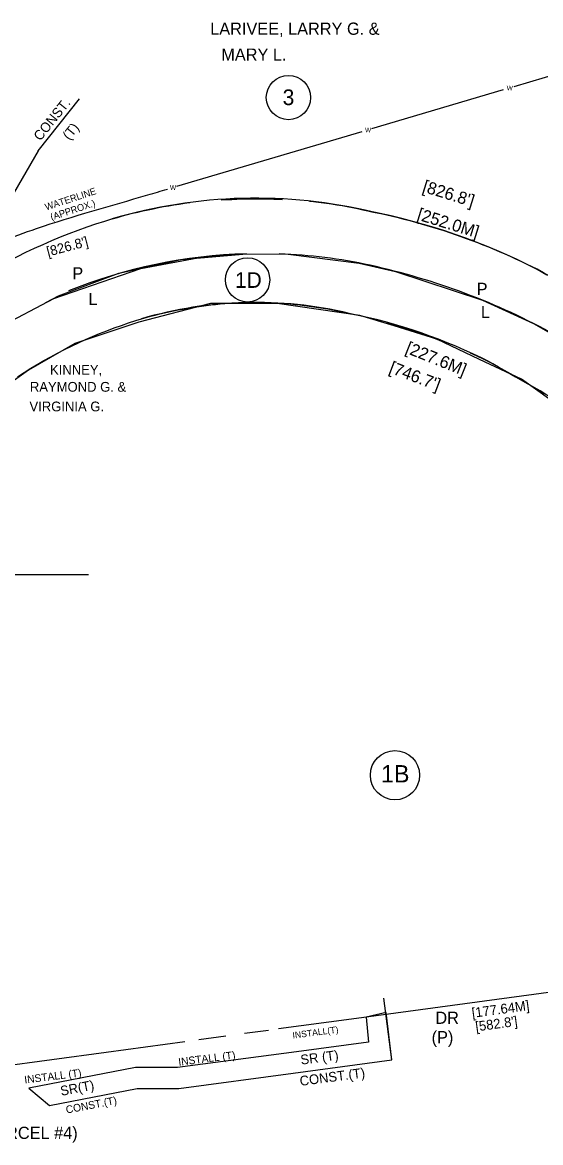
# Model space of a CAD drawing. Extents: x 624 to 1448, y 1599 to 1865.
# Drawn here: x 1071.5 to 1147.3, y 1694.1 to 1857.9 of the extents above; entities that cross this region are included whole.
import ezdxf

# ---------------------------------------------------------------- set-up
doc = ezdxf.new("R2010")
doc.units = 0
for name, color, linetype in [('C_I', 7, 'Continuous'), ('C_TIC', 7, 'Continuous'), ('L_A', 7, 'Continuous'), ('L_C', 7, 'Continuous'), ('L_I', 7, 'Continuous'), ('Level 20', 7, 'Continuous'), ('ODIML_P', 7, 'Continuous')]:
    doc.layers.add(name, color=color, linetype=linetype)

msp = doc.modelspace()

# ---------------------------------------------------------------- linework, layer by layer
at = {"layer": 'C_I'}
for p, q in [((1143.46, 1848.56), (1150.35, 1850.6)), ((1122.63, 1842.39), (1141.9, 1848.1)), ((1073.8, 1839.17), (1079.89, 1846.77)), ((1094.12, 1833.96), (1121.21, 1841.98)), ((1073.8, 1839.17), (1063.81, 1821.9))]:
    msp.add_line(p, q, dxfattribs=at)
for points in [[(1111.14, 1704.26), (1125.57, 1706.19), (1124.39, 1715.24)], [(1090.58, 1702.03), (1094.42, 1702.03), (1111.14, 1704.26)], [(1075.49, 1699.53), (1088.31, 1702.03), (1090.58, 1702.03)]]:
    msp.add_lwpolyline(points, dxfattribs=at)
msp.add_spline([(1063.22, 1823.93), (1073.58, 1827.78), (1089.86, 1832.7), (1092.73, 1833.55)], degree=3, dxfattribs=at)
at = {"layer": 'C_TIC'}
for p, q in [((1119.66, 1712.21), (1156.34, 1717.18)), ((1108.99, 1710.77), (1119.66, 1712.21)), ((1103.99, 1710.09), (1107.51, 1710.56)), ((1083.77, 1707.35), (1095.29, 1708.91)), ((1097.31, 1709.18), (1101.26, 1709.72)), ((1047.93, 1702.5), (1083.77, 1707.35))]:
    msp.add_line(p, q, dxfattribs=at)
at = {"layer": 'L_A'}
for points in [[(1068.14, 1813.35), (1076.1, 1817.56), (1088.82, 1821.95), (1097.94, 1823.65), (1104.33, 1824.09), (1110.38, 1824.03), (1120.8, 1822.73), (1126.12, 1821.52), (1138.82, 1817.31), (1146.28, 1813.9), (1154.59, 1809.17)], [(1150.85, 1801.23), (1144.54, 1805.75), (1138.38, 1808.63), (1132.15, 1811.59), (1125.92, 1813.54), (1120.89, 1815.06), (1108.79, 1816.82), (1099.05, 1816.82), (1088.53, 1814.09), (1079.19, 1810.97), (1072.4, 1807.06), (1066.34, 1802.78)]]:
    msp.add_lwpolyline(points, dxfattribs=at)
at = {"layer": 'L_C'}
msp.add_line((1050.04, 1777.2), (1081.2, 1777.2), dxfattribs=at)
for centre, radius in [((1110.44, 1846.94), 3.24), ((1104.46, 1820.28), 3.24), ((1126.02, 1747.83), 3.6)]:
    msp.add_circle(centre, radius, dxfattribs=at)
at = {"layer": 'L_I'}
msp.add_lwpolyline([(1074.94, 1816.96), (1076.79, 1817.92), (1085.63, 1821.24), (1094.76, 1823.26), (1104.33, 1824.09)], dxfattribs=at)
for centre, radius, start, end in [((1106.39, 1749.13), 75, 91.631, 112.0208), ((1106.39, 1749.13), 75, 77.7037, 87.9317), ((1101.07, 1724.7), 100, 61.0375, 77.7037)]:
    msp.add_arc(centre, radius, start, end, dxfattribs=at)
at = {"layer": 'Level 20'}
msp.add_lwpolyline([(1072.47, 1702.05), (1075.49, 1699.53), (1088.31, 1702.03), (1094.42, 1702.03), (1111.14, 1704.26), (1125.57, 1706.19), (1124.75, 1713.13), (1121.79, 1712.47), (1122.16, 1708.81), (1111.62, 1707.4), (1094.21, 1705.07), (1088.08, 1705.09)], close=True, dxfattribs=at)
at = {"layer": 'ODIML_P'}
for points in [[(1070.8, 1823.7), (1072.04, 1824.31), (1073.29, 1824.9), (1074.55, 1825.47), (1075.81, 1826.02), (1077.09, 1826.55), (1078.38, 1827.06), (1079.67, 1827.55), (1080.97, 1828.01), (1082.28, 1828.46), (1083.6, 1828.88), (1084.6, 1829.18), (1084.66, 1829.2), (1085.41, 1829.42), (1086.15, 1829.62), (1086.9, 1829.82), (1087.64, 1830.01), (1088.39, 1830.19), (1089.15, 1830.37), (1089.9, 1830.53), (1090.66, 1830.69), (1091.41, 1830.84), (1092.17, 1830.99), (1092.93, 1831.12), (1093.69, 1831.25), (1094.45, 1831.37), (1095.22, 1831.48), (1095.98, 1831.59), (1096.01, 1831.59)], [(1100.61, 1831.97), (1101.37, 1832.01), (1102.14, 1832.05), (1102.91, 1832.09), (1103.68, 1832.11), (1104.45, 1832.13), (1105.22, 1832.13), (1105.99, 1832.13), (1106.76, 1832.13), (1107.53, 1832.11), (1108.3, 1832.09), (1109.07, 1832.06), (1109.59, 1832.03)], [(1113.54, 1831.79), (1113.69, 1831.77), (1114.46, 1831.69), (1115.23, 1831.59), (1115.99, 1831.49), (1116.75, 1831.38), (1117.52, 1831.26), (1118.28, 1831.13), (1119.04, 1830.99), (1119.8, 1830.85), (1120.55, 1830.7), (1121.31, 1830.54), (1122.06, 1830.37), (1122.81, 1830.2), (1122.85, 1830.19), (1122.27, 1830.32), (1123.12, 1830.15), (1123.96, 1829.97), (1124.81, 1829.78), (1125.66, 1829.59), (1126.5, 1829.38), (1127.34, 1829.17), (1128.18, 1828.95), (1129.02, 1828.73), (1129.85, 1828.49), (1130.68, 1828.25), (1131.51, 1828), (1132.34, 1827.75), (1133.17, 1827.48), (1133.99, 1827.21), (1134.81, 1826.93), (1135.63, 1826.64), (1136.44, 1826.35), (1137.26, 1826.05), (1138.07, 1825.74), (1138.87, 1825.42), (1139.68, 1825.1), (1140.48, 1824.76), (1141.28, 1824.42), (1142.07, 1824.08), (1142.86, 1823.72), (1143.65, 1823.36), (1144.43, 1822.99), (1145.22, 1822.62), (1145.99, 1822.23), (1146.77, 1821.84), (1146.82, 1821.82), (1148.25, 1821.02)], [(1058.72, 1816.36), (1062.43, 1818.85), (1063.59, 1819.6), (1064.77, 1820.33), (1065.95, 1821.05), (1067.14, 1821.74), (1068.35, 1822.41), (1069.57, 1823.06), (1070.8, 1823.7), (1072.04, 1824.31), (1073.29, 1824.9), (1074.55, 1825.47), (1075.81, 1826.02), (1077.09, 1826.55), (1078.38, 1827.06), (1079.67, 1827.55), (1080.97, 1828.01), (1082.28, 1828.46), (1083.6, 1828.88), (1084.6, 1829.18)], [(1073.24, 1807.65), (1073.7, 1807.92), (1074.67, 1808.49), (1075.66, 1809.04), (1076.66, 1809.57), (1077.66, 1810.09), (1078.68, 1810.59), (1079.7, 1811.08), (1080.73, 1811.54), (1081.77, 1811.99), (1082.81, 1812.43), (1083.86, 1812.84), (1084.92, 1813.24), (1085.99, 1813.62), (1087.06, 1813.99), (1088.13, 1814.33), (1088.95, 1814.58), (1089.62, 1814.77), (1090.28, 1814.95), (1090.94, 1815.12), (1091.61, 1815.29), (1092.28, 1815.45), (1092.95, 1815.6), (1093.63, 1815.75), (1094.3, 1815.88), (1094.98, 1816.01), (1095.66, 1816.13), (1096.34, 1816.24), (1097.02, 1816.34), (1097.7, 1816.44), (1098.38, 1816.53), (1099.06, 1816.61), (1099.75, 1816.68), (1100.43, 1816.75), (1101.12, 1816.8), (1101.81, 1816.85), (1102.49, 1816.89), (1103.18, 1816.92), (1103.87, 1816.95), (1104.56, 1816.96), (1105.25, 1816.97), (1105.93, 1816.97), (1106.62, 1816.96), (1107.31, 1816.95), (1108, 1816.92), (1108.69, 1816.89), (1109.37, 1816.85), (1110.06, 1816.81), (1110.75, 1816.75), (1111.43, 1816.69), (1112.12, 1816.62), (1112.8, 1816.54), (1113.48, 1816.45), (1114.16, 1816.35), (1114.85, 1816.25), (1115.52, 1816.14), (1116.2, 1816.02), (1116.88, 1815.89), (1117.55, 1815.76), (1118.23, 1815.62), (1118.9, 1815.47), (1119.32, 1815.37), (1120.1, 1815.21), (1120.38, 1815.15)], [(1070.82, 1806.12), (1071.77, 1806.74), (1072.73, 1807.34), (1073.7, 1807.92), (1074.67, 1808.49), (1075.66, 1809.04), (1076.66, 1809.57), (1077.66, 1810.09), (1078.68, 1810.59), (1079.7, 1811.08), (1080.73, 1811.54), (1081.77, 1811.99), (1082.81, 1812.43), (1083.86, 1812.84), (1084.92, 1813.24), (1085.99, 1813.62), (1087.06, 1813.99), (1088.13, 1814.33), (1088.95, 1814.58)], [(1124.85, 1813.99), (1125.47, 1813.82), (1126.23, 1813.6), (1126.99, 1813.37), (1127.75, 1813.14), (1128.51, 1812.89), (1129.26, 1812.64), (1130.01, 1812.38), (1130.75, 1812.12), (1131.5, 1811.85), (1132.24, 1811.57), (1132.98, 1811.28), (1133.36, 1811.13)], [(1137.03, 1809.63), (1137.38, 1809.47), (1138.1, 1809.13), (1138.81, 1808.79), (1139.52, 1808.43), (1139.89, 1808.25), (1139.45, 1808.48), (1140.85, 1807.7), (1142.24, 1806.92), (1143.64, 1806.12), (1145.02, 1805.33), (1146.41, 1804.52), (1147.79, 1803.71)]]:
    msp.add_lwpolyline(points, dxfattribs=at)
for centre, radius, start, end in [((1105.62, 1757.75), 74.47, 76.6263, 106.344), ((1104.1, 1738.14), 93.95, 62.9581, 78.8521), ((984.41, 1527.8), 335.89, 55.3797, 61.0858), ((1105.62, 1757.75), 59.23, 76.6263, 106.344), ((1104.1, 1738.14), 78.71, 62.9581, 78.8521), ((984.41, 1527.8), 320.65, 55.3797, 61.0858)]:
    msp.add_arc(centre, radius, start, end, dxfattribs=at)

# ---------------------------------------------------------------- texts
at = {"layer": 'C_I'}
for s, height, p in [('W', 0.7, (1142.36, 1847.99)), ('W', 0.7, (1121.63, 1841.86)), ('W', 0.7, (1093.1, 1833.43)), ('DR', 1.783, (1131.93, 1711.47)), ('(P)', 1.783, (1131.38, 1708.63))]:
    msp.add_text(s, height=height, dxfattribs=at).set_placement(p)
for s, height, rotation, p in [('CONST.', 1.426, 51.2877, (1074.14, 1840.5)), ('(T)', 1.426, 51.2877, (1078.38, 1840.61)), ("[826.8']", 1.783, 342.8049, (1129.92, 1833.2)), ('WATERLINE', 1, 18.1737, (1075, 1830.42)), ('(APPROX.)', 1, 18.1737, (1075.8, 1828.95)), ('[252.0M]', 1.783, 342.8049, (1129.13, 1829.12)), ("[826.8']", 1.426, 14.8049, (1075.27, 1823.68)), ('[227.6M]', 1.783, 338.2557, (1127.42, 1809.65)), ("[746.7']", 1.783, 339.2557, (1125.03, 1806.76)), ('[177.64M]', 1.426, 7.7461, (1137.35, 1712.35)), ("[582.8']", 1.426, 7.7461, (1137.88, 1710.36)), ('INSTALL(T)', 0.948, 7.5025, (1111.09, 1709.31)), ('INSTALL (T)', 1.12, 7.1875, (1094.4, 1705.33)), ('SR (T)', 1.422, 7.5025, (1112.29, 1705.5)), ('INSTALL (T)', 1.12, 7.1875, (1071.87, 1702.73)), ('CONST.(T)', 1.422, 7.5025, (1112.18, 1702.39)), ('SR(T)', 1.4, 10.8663, (1077.21, 1700.94)), ('CONST.(T)', 1.12, 10.8663, (1077.98, 1698.34))]:
    msp.add_text(s, height=height, rotation=rotation, dxfattribs=at).set_placement(p)
at = {"layer": 'L_A'}
for s, height, p in [('LARIVEE, LARRY G. &', 1.783, (1098.99, 1856.12)), ('MARY L.', 1.783, (1100.61, 1852.33)), ('KINNEY,', 1.426, (1075.56, 1806.42)), ('RAYMOND G. &', 1.4264, (1072.61, 1803.92)), ('VIRGINIA G.', 1.4264, (1072.55, 1801.05)), ('(PARCEL #4)', 1.783, (1065.16, 1694.64))]:
    msp.add_text(s, height=height, dxfattribs=at).set_placement(p)
at = {"layer": 'L_C'}
for s, height, p in [('3', 2.29, (1109.59, 1845.84)), ('1D', 2.286, (1102.62, 1819.11)), ('1B', 2.54, (1123.98, 1746.77))]:
    msp.add_text(s, height=height, dxfattribs=at).set_placement(p)
at = {"layer": 'L_I'}
for s, p in [('P', (1078.82, 1820.34)), ('P', (1137.97, 1818.07)), ('L', (1081.18, 1816.6)), ('L', (1138.58, 1814.68))]:
    msp.add_text(s, height=1.78, dxfattribs=at).set_placement(p)

doc.saveas('drawing.dxf')
